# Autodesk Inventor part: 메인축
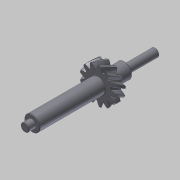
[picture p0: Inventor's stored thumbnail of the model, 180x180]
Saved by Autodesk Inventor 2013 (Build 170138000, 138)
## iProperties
Created: 2018-07
Part Number: 메인축
Material: 강철
Document SubType Name: Modeling
Designer: mduedu
Categories: <?xml version="1.0" encoding="UTF-16"?> <MemberInstance><Categories><FamilyTemplate><FamilyTemplateParameter ValueType="xs:double" Id="1" ObjectReferenceKey="da
Density: 7.85 g/cm^3
Mass: 182.309 g
Surface Area: 79.8926 cm^2
Volume: 23.2241 cm^3
CustomPartVersion: 1
Author: mduedu
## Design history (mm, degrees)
sketch "Sketch1"
  geometry: C1 r 17.232 at (0, 0)
  constraints: 1 centre point
  dimensions: "d0" = 34.46497 diameter of C1 (= da_da)
extrude "Extrusion1" new body sketch "Sketch1" distance "d1" = 10 (= da_b); taper "d2" = 0 deg
workplane "Work Plane2"
sketch "Sketch2"
  geometry: C1 r 17.232 at (0, 0) reference; C2 r 15.087 at (0, 0)
  constraints: 1 centre point, 1 coincident
  dimensions: "d3" = 30.17368 diameter of C2 (= da_dw)
feature "피치 지름" sketch "Sketch2" dims "d4" = 10, "d5" = 0
workplane "Work Plane8"
workplane "Work Plane9"
feature "스퍼 기어" dims "da_b" = 10, "da_d" = 30.02221, "da_aw" = 44.1, "da_da" = 34.46497, "da_df" = 25.47121, "da_dw" = 30.17368, angle "da_beta" = 30 deg, "da_lefttooth" = 0, "da_righttooth" = 10
sketch "스케치3"
  geometry: C1 r 7.5 at (0, 0); 1 further point
  constraints: 1 centre point, 1 coincident
  dimensions: "d49" = 15 diameter of C1
extrude "돌출2" join sketch "스케치3" distance "d50" = 64; taper "d51" = 0 deg
sketch "스케치4"
  geometry: C1 r 4 at (0, 0); 1 further point
  constraints: 1 centre point, 1 coincident
  dimensions: "d52" = 8 diameter of C1
extrude "돌출3" join sketch "스케치4" distance "d53" = 7; taper "d54" = 0 deg
sketch "스케치5"
  geometry: C1 r 7.5 at (0, 0) reference; C2 r 7.5 at (0, 0) reference; 1 further point
extrude "돌출4" join sketch "스케치5" distance "d55" = 16; taper "d56" = 0 deg
sketch "스케치6"
  geometry: C1 r 4 at (0, 0); 1 further point
  constraints: 1 centre point, 1 coincident
  dimensions: "d57" = 8 diameter of C1
extrude "돌출5" join sketch "스케치6" distance "d58" = 30; taper "d59" = 0 deg
chamfer "모따기1" distance "d60" = 0.5; stored, may be unused: second distance "d61" = 2, angle "d62" = 45 deg
fillet "모깎기1" dims "d63" = 0.5
body "Solid1"
body "Srf1"
node "투영된 루프1"
other parameters: "d16" = 44.1 (= da_aw), "d17" = 0, "d34" = 2.41661 (computed from da_z), "d39" = 0, "d41" = 0, "d43" = 44.1 (= da_aw), "d46" = 44.1 (= da_aw), "d47" = 0, "d48" = 0
